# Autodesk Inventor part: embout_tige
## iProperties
Shininess: 64.0
Length Units: 11269
Angle Units: 11279
Time Units: 11290
Mass Units: 11283
Length Display Precision: 3
Angle Display Precision: 2
Compacted: True
Part Number: embout_tige
Document SubType Name: Modeling
Created: 2004-05
Material: Par défaut
Designer: David
Density: 0.0
Volumn: 0.0
Area: 0.0
PropertySet Name: Model Information
Control State: 0
Master: False
Checked Out: False
Author: David
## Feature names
1. Révolution1 [Revolution]
2. Révolution2 [Revolution]
